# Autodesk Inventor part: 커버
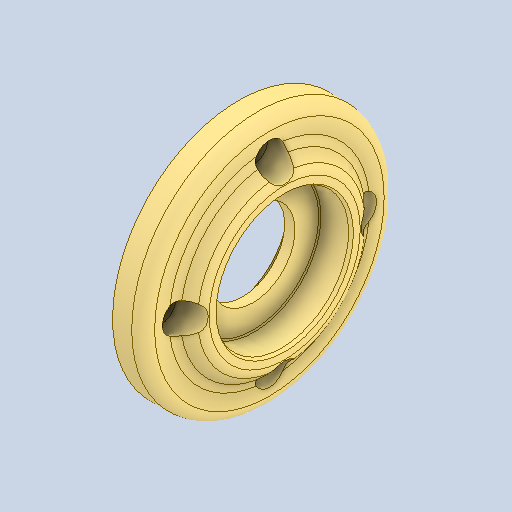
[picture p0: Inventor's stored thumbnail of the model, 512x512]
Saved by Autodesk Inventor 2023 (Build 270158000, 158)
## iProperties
Created: 2026-06
Part Number: 커버
Material: 알루미늄 6061
Document SubType Name: Modeling
Designer: home
Density: 2.7 g/cm^3
Appearance: 기본값
Sending System: Autodesk Inventor 2027
Preprocessor: ST-DEVELOPER v20.1
Author: jhkim
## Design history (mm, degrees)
feature "솔리드1"
node "솔리드2"
